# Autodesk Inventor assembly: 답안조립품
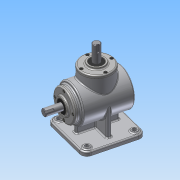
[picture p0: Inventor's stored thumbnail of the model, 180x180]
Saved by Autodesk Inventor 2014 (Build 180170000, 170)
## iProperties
Created: 2015-07
Part Number: 답안조립품
Document SubType Name: Assembly
Designer: net
Author: net
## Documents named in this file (14)
- C:\Users\net\Desktop\450705V1026\답안조립품.iam
- C:\Users\net\Desktop\450705V1026\본체.ipt
- C:\Users\net\Desktop\450705V1026\메인 축.ipt
- 메인 축.ipt
- C:\Users\net\Desktop\450705V1026\메인 베벨기어.ipt
- C:\Users\net\Desktop\450705V1026\키 5x5.ipt
- C:\Users\net\Desktop\450705V1026\서브 축.ipt
- 서브 축.ipt
- C:\Users\net\Desktop\450705V1026\서브 베벨기어.ipt
- C:\Users\net\Desktop\450705V1026\키 4x4.ipt
- C:\Users\net\Desktop\450705V1026\베어링 6203.ipt
- C:\Users\net\Desktop\450705V1026\커버.ipt
- C:\Users\net\Desktop\450705V1026\오일실.ipt
- C:\Users\net\Desktop\450705V1026\M4.ipt
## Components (8 placed, 1 different names)
1. M4:2
2. M4:3
3. M4:4
4. M4:5
5. M4:1
6. M4:6
7. M4:7
8. M4:8
